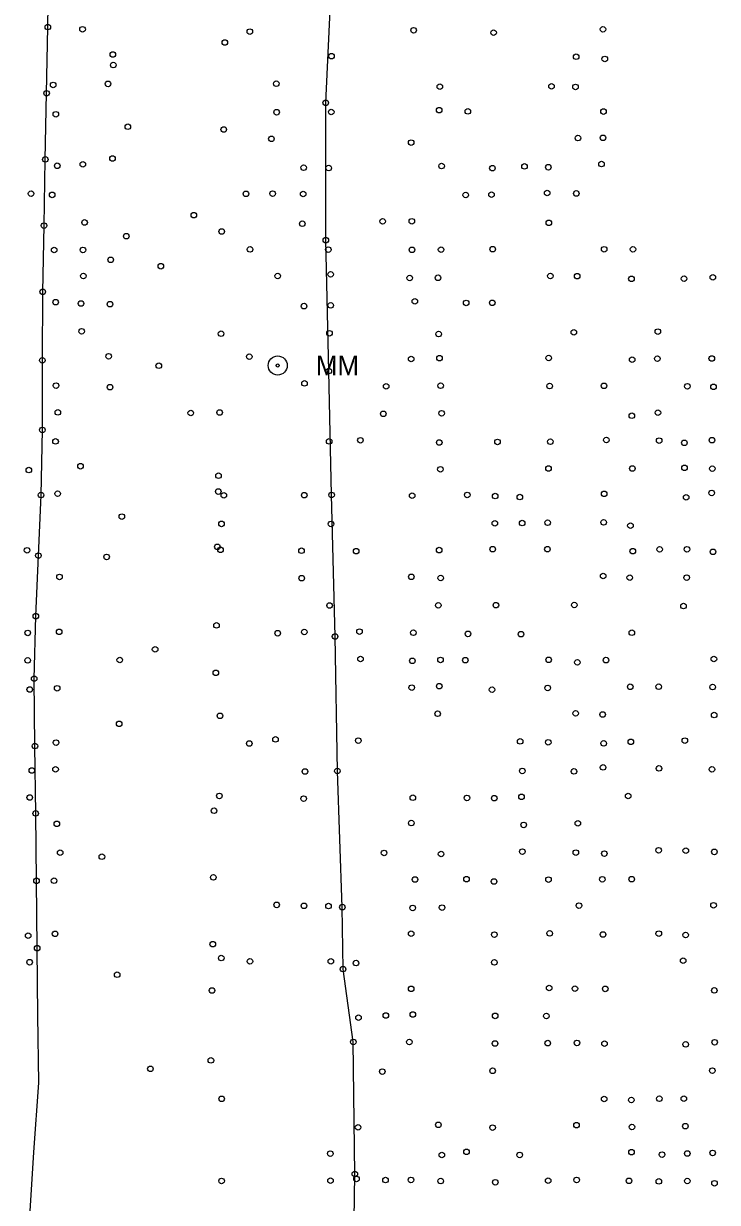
# Model space of a CAD drawing. Extents: x 20503438 to 20508873, y 7964251 to 7984667.
# Drawn here: x 20506616.9 to 20506866.4, y 7966287.3 to 7966710.9 of the extents above; entities that cross this region are included whole.
import ezdxf

# ---------------------------------------------------------------- set-up
doc = ezdxf.new("R2010")
doc.units = 0
for name, color, linetype in [('SurDrainageArrowDown', 7, 'Continuous'), ('SurDrainageArrowUp', 7, 'Continuous'), ('SurRoadPoints', 7, 'Continuous'), ('SurSurveyPoints', 7, 'Continuous')]:
    doc.layers.add(name, color=color, linetype=linetype)

msp = doc.modelspace()

# ---------------------------------------------------------------- linework, layer by layer
at = {"layer": 'SurDrainageArrowDown'}
msp.add_lwpolyline([(20506616.88, 7966180.41), (20506617.4, 7966205.4), (20506617.92, 7966230.4), (20506618.45, 7966255.39), (20506618.97, 7966280.39), (20506620.54, 7966305.33), (20506622.35, 7966330.27), (20506622.07, 7966354.47), (20506621.79, 7966378.67), (20506621.52, 7966402.88), (20506621.24, 7966427.08), (20506620.96, 7966451.29), (20506620.68, 7966475.49), (20506621.28, 7966497.96), (20506622.23, 7966519.72), (20506623.18, 7966541.47), (20506623.65, 7966564.87), (20506623.65, 7966589.87), (20506623.79, 7966614.5), (20506624.24, 7966638.28), (20506624.7, 7966662.06), (20506625.16, 7966685.84), (20506625.61, 7966709.62), (20506625.94, 7966733.94)], dxfattribs=at)
at = {"layer": 'SurDrainageArrowUp'}
msp.add_lwpolyline([(20506748.37, 7966102.43), (20506739.98, 7966120.94), (20506735.03, 7966132), (20506735.65, 7966158.21), (20506738.35, 7966207.5), (20506735.41, 7966256.62), (20506736, 7966297.52), (20506735.47, 7966344.97), (20506731.78, 7966371.15), (20506731.51, 7966393.42), (20506729.75, 7966442.32), (20506728.92, 7966490.67), (20506727.65, 7966541.52), (20506726.65, 7966586.02), (20506725.58, 7966633.07), (20506725.56, 7966682.41), (20506728.02, 7966733.71)], dxfattribs=at)
at = {"layer": 'SurRoadPoints'}
for radius in [3.43, 0.571]:
    msp.add_circle((20506708.27, 7966588.01), radius, dxfattribs=at)
at = {"layer": 'SurSurveyPoints'}
for centre in [(20506625.61, 7966709.62), (20506638.1, 7966708.83), (20506757.15, 7966708.48), (20506825.26, 7966708.81), (20506689.28, 7966704.08), (20506698.26, 7966707.98), (20506785.91, 7966707.6), (20506648.97, 7966699.76), (20506649.15, 7966695.97), (20506727.64, 7966699.16), (20506815.62, 7966698.95), (20506825.9, 7966698.17), (20506627.51, 7966688.83), (20506647.26, 7966689.2), (20506707.77, 7966689.27), (20506766.6, 7966688.2), (20506806.76, 7966688.32), (20506815.37, 7966688.11), (20506625.16, 7966685.84), (20506707.89, 7966679.02), (20506725.56, 7966682.41), (20506727.53, 7966679.11), (20506766.36, 7966679.76), (20506776.65, 7966679.32), (20506825.44, 7966679.26), (20506628.47, 7966678.28), (20506654.38, 7966673.8), (20506688.88, 7966672.82), (20506706.02, 7966669.47), (20506756.28, 7966668.12), (20506816.25, 7966669.74), (20506825.27, 7966669.83), (20506624.7, 7966662.06), (20506648.87, 7966662.39), (20506628.99, 7966659.78), (20506638.19, 7966660.3), (20506717.61, 7966659.09), (20506726.62, 7966658.97), (20506767.21, 7966659.68), (20506785.5, 7966658.92), (20506797.05, 7966659.55), (20506805.61, 7966659.26), (20506824.73, 7966660.39), (20506619.57, 7966649.77), (20506627.17, 7966649.32), (20506696.85, 7966649.7), (20506706.45, 7966649.78), (20506717.44, 7966649.63), (20506775.89, 7966649.28), (20506785.18, 7966649.39), (20506805.2, 7966649.99), (20506815.67, 7966649.84), (20506678.1, 7966642.03), (20506624.24, 7966638.28), (20506638.82, 7966639.42), (20506717.11, 7966638.95), (20506746.01, 7966639.83), (20506756.53, 7966639.84), (20506805.8, 7966639.27), (20506653.82, 7966634.5), (20506688.14, 7966636.15), (20506725.58, 7966633.07), (20506627.87, 7966629.52), (20506638.23, 7966629.54), (20506698.33, 7966629.73), (20506726.46, 7966629.66), (20506756.56, 7966629.57), (20506767.04, 7966629.64), (20506785.6, 7966629.83), (20506825.68, 7966629.78), (20506836.04, 7966629.77), (20506648.22, 7966625.98), (20506666.24, 7966623.69), (20506638.39, 7966620.18), (20506708.28, 7966620.18), (20506727.32, 7966620.78), (20506755.75, 7966619.46), (20506765.93, 7966619.54), (20506806.34, 7966620.18), (20506815.96, 7966620.12), (20506864.78, 7966619.71), (20506835.49, 7966619.15), (20506854.42, 7966619.22), (20506623.79, 7966614.5), (20506757.6, 7966611.08), (20506628.43, 7966610.79), (20506637.55, 7966610.28), (20506647.95, 7966610.05), (20506717.76, 7966609.36), (20506727.33, 7966609.62), (20506776.06, 7966610.51), (20506785.43, 7966610.52), (20506637.77, 7966600.32), (20506687.92, 7966599.43), (20506726.89, 7966599.61), (20506766.16, 7966599.31), (20506814.76, 7966599.93), (20506845, 7966600.2), (20506623.65, 7966589.87), (20506647.48, 7966591.34), (20506698.06, 7966591.2), (20506756.27, 7966590.36), (20506766.45, 7966590.66), (20506805.74, 7966590.71), (20506835.74, 7966590.11), (20506844.83, 7966590.48), (20506864.38, 7966590.55), (20506665.51, 7966587.93), (20506726.65, 7966586.02), (20506717.92, 7966581.59), (20506628.57, 7966580.8), (20506647.99, 7966580.23), (20506747.27, 7966580.54), (20506766.86, 7966580.75), (20506806.07, 7966580.64), (20506825.63, 7966580.73), (20506855.61, 7966580.56), (20506865.01, 7966580.35), (20506629.19, 7966571.18), (20506677.01, 7966570.96), (20506687.39, 7966571.12), (20506746.25, 7966570.67), (20506767.22, 7966570.86), (20506835.65, 7966569.96), (20506845.01, 7966571.07), (20506623.65, 7966564.87), (20506628.39, 7966560.74), (20506726.79, 7966560.76), (20506738.03, 7966561.17), (20506766.37, 7966560.34), (20506787.33, 7966560.57), (20506806.33, 7966560.63), (20506826.49, 7966561.25), (20506845.46, 7966561.03), (20506854.53, 7966560.25), (20506864.44, 7966561.2), (20506637.37, 7966551.83), (20506618.77, 7966550.44), (20506686.99, 7966548.42), (20506766.8, 7966550.73), (20506805.66, 7966551.02), (20506835.83, 7966551.02), (20506854.58, 7966551.24), (20506864.57, 7966550.95), (20506623.18, 7966541.47), (20506629.14, 7966541.98), (20506686.9, 7966542.73), (20506688.9, 7966541.37), (20506717.82, 7966541.43), (20506727.65, 7966541.52), (20506756.62, 7966541.25), (20506776.44, 7966541.52), (20506786.5, 7966541.1), (20506795.34, 7966540.74), (20506825.7, 7966541.91), (20506855.19, 7966540.65), (20506864.35, 7966542.24), (20506652.22, 7966533.72), (20506688.05, 7966531.11), (20506727.47, 7966531.09), (20506786.35, 7966531.31), (20506796.2, 7966531.4), (20506805.36, 7966531.53), (20506825.5, 7966531.65), (20506835.13, 7966530.47), (20506686.59, 7966522.86), (20506785.6, 7966522.04), (20506805.28, 7966522.03), (20506845.63, 7966521.98), (20506855.45, 7966522), (20506618.15, 7966521.63), (20506622.23, 7966519.72), (20506646.74, 7966519.25), (20506687.7, 7966521.8), (20506716.84, 7966521.46), (20506736.48, 7966521.32), (20506766.35, 7966521.69), (20506835.97, 7966521.3), (20506864.81, 7966521.08), (20506629.79, 7966512.05), (20506716.92, 7966511.62), (20506756.34, 7966512.1), (20506766.9, 7966511.66), (20506825.32, 7966512.39), (20506834.89, 7966511.78), (20506855.38, 7966511.82), (20506726.93, 7966501.78), (20506766.02, 7966501.84), (20506786.75, 7966501.92), (20506814.95, 7966501.96), (20506854.21, 7966501.59), (20506621.28, 7966497.96), (20506629.67, 7966492.32), (20506686.25, 7966494.65), (20506717.84, 7966492.26), (20506737.71, 7966492.41), (20506618.39, 7966491.94), (20506708.28, 7966491.83), (20506728.92, 7966490.67), (20506757.07, 7966492.01), (20506776.71, 7966491.59), (20506795.77, 7966491.5), (20506835.64, 7966492.01), (20506664.19, 7966486.04), (20506618.37, 7966482.07), (20506651.48, 7966482.21), (20506738.04, 7966482.56), (20506756.72, 7966481.9), (20506766.83, 7966482.24), (20506775.75, 7966482.15), (20506805.72, 7966482.26), (20506816.04, 7966481.37), (20506826.33, 7966482.17), (20506865.14, 7966482.56), (20506620.68, 7966475.49), (20506686.03, 7966477.61), (20506619.11, 7966471.61), (20506628.98, 7966472.04), (20506756.49, 7966472.29), (20506766.37, 7966472.81), (20506785.35, 7966471.54), (20506805.38, 7966472.17), (20506835.06, 7966472.59), (20506845.3, 7966472.6), (20506864.68, 7966472.48), (20506765.8, 7966462.89), (20506815.43, 7966463.05), (20506825.12, 7966462.64), (20506651.26, 7966459.26), (20506687.51, 7966462.15), (20506865.25, 7966462.43), (20506620.96, 7966451.29), (20506628.57, 7966452.52), (20506698.05, 7966452.22), (20506707.49, 7966453.69), (20506737.26, 7966453.25), (20506795.49, 7966452.97), (20506805.57, 7966452.65), (20506825.53, 7966452.25), (20506835.29, 7966452.81), (20506854.68, 7966453.24), (20506619.86, 7966442.52), (20506628.39, 7966442.92), (20506718.07, 7966442.15), (20506729.75, 7966442.32), (20506796.25, 7966442.34), (20506814.83, 7966442.17), (20506825.3, 7966443.62), (20506845.39, 7966443.25), (20506864.44, 7966442.92), (20506687.31, 7966433.38), (20506795.94, 7966433.03), (20506834.33, 7966433.34), (20506619.11, 7966432.79), (20506717.61, 7966432.4), (20506756.88, 7966432.72), (20506776.33, 7966432.64), (20506786.15, 7966432.58), (20506621.24, 7966427.08), (20506685.38, 7966428.04), (20506628.83, 7966423.35), (20506756.32, 7966423.63), (20506796.75, 7966422.96), (20506816.23, 7966423.52), (20506630.03, 7966412.98), (20506746.54, 7966412.89), (20506767.04, 7966412.5), (20506796.27, 7966413.36), (20506815.51, 7966413.01), (20506825.75, 7966412.66), (20506845.26, 7966413.85), (20506855.03, 7966413.7), (20506865.32, 7966413.26), (20506645.05, 7966411.52), (20506685.13, 7966404.1), (20506757.66, 7966403.33), (20506776.19, 7966403.47), (20506805.66, 7966403.31), (20506825.02, 7966403.42), (20506835.59, 7966403.45), (20506621.52, 7966402.88), (20506627.86, 7966402.91), (20506786.08, 7966402.64), (20506707.91, 7966394.22), (20506717.71, 7966393.88), (20506726.55, 7966393.79), (20506731.51, 7966393.42), (20506756.83, 7966393.13), (20506767.4, 7966393.25), (20506816.61, 7966393.96), (20506865.02, 7966394.09), (20506618.54, 7966383.16), (20506628.22, 7966383.81), (20506756.26, 7966383.87), (20506786.21, 7966383.55), (20506806.11, 7966383.98), (20506825.29, 7966383.58), (20506845.32, 7966383.91), (20506854.97, 7966383.41), (20506621.79, 7966378.67), (20506684.93, 7966380.11), (20506619.05, 7966373.62), (20506687.97, 7966375.11), (20506698.29, 7966373.93), (20506727.37, 7966373.93), (20506854.09, 7966374.17), (20506731.78, 7966371.15), (20506736.44, 7966373.31), (20506786.2, 7966373.56), (20506650.53, 7966369.13), (20506684.65, 7966363.47), (20506756.26, 7966364.06), (20506805.92, 7966364.37), (20506815.16, 7966364.13), (20506826.07, 7966364.04), (20506865.29, 7966363.49), (20506737.32, 7966353.69), (20506747.17, 7966354.48), (20506756.86, 7966354.83), (20506786.49, 7966354.34), (20506804.9, 7966354.29), (20506735.47, 7966344.97), (20506755.64, 7966344.96), (20506786.44, 7966344.41), (20506805.4, 7966344.56), (20506815.91, 7966344.63), (20506825.79, 7966344.35), (20506855.01, 7966344.1), (20506865.42, 7966344.87), (20506684.25, 7966338.35), (20506662.51, 7966335.32), (20506745.88, 7966334.33), (20506785.56, 7966334.62), (20506864.59, 7966334.68), (20506688.13, 7966324.54), (20506825.69, 7966324.48), (20506835.46, 7966324.11), (20506845.53, 7966324.57), (20506854.32, 7966324.6), (20506766.07, 7966315.21), (20506815.73, 7966315.07), (20506835.67, 7966314.42), (20506854.89, 7966314.72), (20506737.19, 7966314.3), (20506785.55, 7966314.19), (20506727.18, 7966304.86), (20506767.29, 7966304.36), (20506776.18, 7966305.48), (20506795.32, 7966304.38), (20506835.5, 7966305.36), (20506846.5, 7966304.5), (20506855.57, 7966304.89), (20506864.69, 7966305.11), (20506736, 7966297.52), (20506688.09, 7966295.04), (20506727.25, 7966295.13), (20506736.6, 7966295.76), (20506747.06, 7966295.34), (20506756.2, 7966295.39), (20506766.91, 7966294.99), (20506786.53, 7966294.57), (20506805.54, 7966295.13), (20506815.77, 7966295.39), (20506834.61, 7966295.09), (20506845.35, 7966294.87), (20506855.58, 7966295.02), (20506865.36, 7966294.19)]:
    msp.add_circle(centre, 1, dxfattribs=at)

# ---------------------------------------------------------------- texts
at = {"layer": 'SurRoadPoints'}
msp.add_text('MM', height=6.995, rotation=360, dxfattribs=at).set_placement((20506721.98, 7966584.51))

doc.saveas('drawing.dxf')
